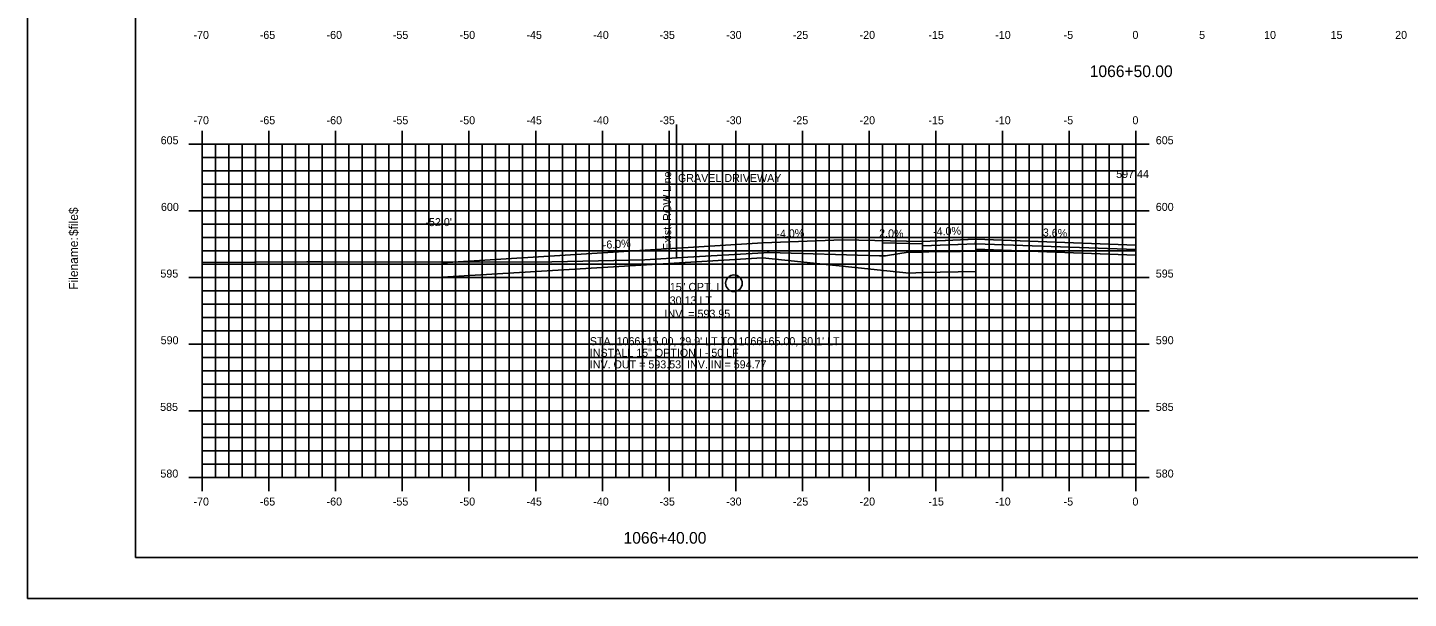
# Model space of a CAD drawing. Extents: x 1067877 to 1068047, y 779716 to 779826.
# Drawn here: x 1067877 to 1067980.5, y 779715.6 to 779758.5 of the extents above; entities that cross this region are included whole.
import ezdxf

# ---------------------------------------------------------------- set-up
doc = ezdxf.new("R2010")
doc.units = 0
for name, color, linetype in [('ANNOTATION', 7, 'Continuous'), ('BORDER', 7, 'Continuous'), ('D_Drainage_Culvert', 7, 'Continuous'), ('D_Roadway_Centerline', 7, 'Continuous'), ('D_Roadway_Centerline_Text', 7, 'Continuous'), ('D_Roadway_Drive_Gravel', 7, 'Continuous'), ('D_Roadway_Drive_SubGrade', 7, 'Continuous'), ('D_Roadway_Edge_Pavement', 7, 'Continuous'), ('D_Roadway_Edge_Shoulder', 7, 'Continuous'), ('D_Roadway_Pavement', 7, 'Continuous'), ('D_Roadway_SubGrade', 7, 'Continuous'), ('D_Text_Standard', 7, 'Continuous'), ('E_ROW_Line', 7, 'Continuous'), ('H_V ANNOTATION', 7, 'Continuous'), ('MAJOR', 7, 'Continuous'), ('MINOR', 7, 'Continuous'), ('PLOT BOUNDARY', 7, 'Continuous'), ('S_Roadway_Centerline', 7, 'Continuous')]:
    doc.layers.add(name, color=color, linetype=linetype)

msp = doc.modelspace()

# ---------------------------------------------------------------- linework, layer by layer
at = {"layer": 'BORDER'}
msp.add_lwpolyline([(1067885.05, 779718.71), (1068045.05, 779718.71), (1068045.05, 779823.71), (1067885.05, 779823.71)], close=True, dxfattribs=at)
at = {"layer": 'D_Drainage_Culvert'}
msp.add_circle((1067929.92, 779739.28), 0.625, dxfattribs=at)
at = {"layer": 'D_Roadway_Centerline'}
msp.add_lwpolyline([(1067944.05, 779742.42), (1067948.04, 779742.58), (1067948.05, 779742.58), (1067948.05, 779742.58), (1067960.05, 779742.15)], dxfattribs=at)
at = {"layer": 'D_Roadway_Drive_Gravel'}
for points in [[(1067944.05, 779742.42), (1067938.08, 779742.55), (1067932.08, 779742.31), (1067908.05, 779740.81)], [(1067944.05, 779742.25), (1067941.05, 779742.32), (1067941.05, 779742.48)]]:
    msp.add_lwpolyline(points, dxfattribs=at)
at = {"layer": 'D_Roadway_Drive_SubGrade'}
msp.add_lwpolyline([(1067944.05, 779740.08), (1067943.05, 779740.05), (1067932.05, 779741.2), (1067908.04, 779739.75), (1067908.04, 779740.87)], dxfattribs=at)
at = {"layer": 'D_Roadway_Edge_Pavement'}
for p, q in [((1067948.05, 779742.58), (1067960.05, 779742.15)), ((1067948.05, 779742.25), (1067960.05, 779741.81))]:
    msp.add_line(p, q, dxfattribs=at)
at = {"layer": 'D_Roadway_Edge_Shoulder'}
msp.add_lwpolyline([(1067948.05, 779742.58), (1067944.05, 779742.42), (1067944.05, 779742.09), (1067948.04, 779742.25)], close=True, dxfattribs=at)
at = {"layer": 'D_Roadway_Pavement'}
msp.add_line((1067948.05, 779741.83), (1067960.05, 779741.4), dxfattribs=at)
at = {"layer": 'D_Roadway_SubGrade'}
msp.add_lwpolyline([(1067948.05, 779740.16), (1067944.05, 779740.08), (1067944.05, 779742.09), (1067948.05, 779742.25), (1067948.05, 779742.09), (1067948.05, 779740.59)], close=True, dxfattribs=at)
at = {"layer": 'E_ROW_Line'}
msp.add_line((1067925.61, 779741.18), (1067925.61, 779751.18), dxfattribs=at)
msp.add_line((1067925.61, 779741.18), (1067925.61, 779751.18), dxfattribs=at)
at = {"layer": 'MAJOR'}
for p, q in [((1067890.05, 779750.71), (1067890.05, 779749.71)), ((1067895.05, 779750.71), (1067895.05, 779749.71)), ((1067900.05, 779750.71), (1067900.05, 779749.71)), ((1067905.05, 779750.71), (1067905.05, 779749.71)), ((1067910.05, 779750.71), (1067910.05, 779749.71)), ((1067915.05, 779750.71), (1067915.05, 779749.71)), ((1067920.05, 779750.71), (1067920.05, 779749.71)), ((1067925.05, 779750.71), (1067925.05, 779749.71)), ((1067930.05, 779750.71), (1067930.05, 779749.71)), ((1067935.05, 779750.71), (1067935.05, 779749.71)), ((1067940.05, 779750.71), (1067940.05, 779749.71)), ((1067945.05, 779750.71), (1067945.05, 779749.71)), ((1067950.05, 779750.71), (1067950.05, 779749.71)), ((1067955.05, 779750.71), (1067955.05, 779749.71)), ((1067960.05, 779750.71), (1067960.05, 779749.71)), ((1067889.04, 779749.71), (1067890.05, 779749.71)), ((1067890.05, 779749.71), (1067960.05, 779749.71)), ((1067890.05, 779724.71), (1067890.05, 779749.71)), ((1067890.05, 779724.71), (1067890.05, 779749.71)), ((1067890.05, 779749.71), (1067960.05, 779749.71)), ((1067895.05, 779724.71), (1067895.05, 779749.71)), ((1067900.05, 779724.71), (1067900.05, 779749.71)), ((1067905.05, 779724.71), (1067905.05, 779749.71)), ((1067910.05, 779724.71), (1067910.05, 779749.71)), ((1067915.05, 779724.71), (1067915.05, 779749.71)), ((1067920.05, 779724.71), (1067920.05, 779749.71)), ((1067925.05, 779724.71), (1067925.05, 779749.71)), ((1067930.05, 779724.71), (1067930.05, 779749.71)), ((1067935.05, 779724.71), (1067935.05, 779749.71)), ((1067940.05, 779724.71), (1067940.05, 779749.71)), ((1067945.05, 779724.71), (1067945.05, 779749.71)), ((1067950.05, 779724.71), (1067950.05, 779749.71)), ((1067955.05, 779724.71), (1067955.05, 779749.71)), ((1067961.05, 779749.71), (1067959.04, 779749.71)), ((1067960.05, 779724.71), (1067960.05, 779749.71)), ((1067960.05, 779724.71), (1067960.05, 779749.71)), ((1067889.04, 779744.71), (1067890.05, 779744.71)), ((1067890.05, 779744.71), (1067960.05, 779744.71)), ((1067961.05, 779744.71), (1067959.04, 779744.71)), ((1067889.04, 779739.71), (1067890.05, 779739.71)), ((1067890.05, 779739.71), (1067960.05, 779739.71)), ((1067961.05, 779739.71), (1067959.04, 779739.71)), ((1067889.04, 779734.71), (1067890.05, 779734.71)), ((1067890.05, 779734.71), (1067960.05, 779734.71)), ((1067961.05, 779734.71), (1067959.04, 779734.71)), ((1067889.04, 779729.71), (1067890.05, 779729.71)), ((1067890.05, 779729.71), (1067960.05, 779729.71)), ((1067961.05, 779729.71), (1067959.04, 779729.71)), ((1067889.04, 779724.71), (1067890.05, 779724.71)), ((1067890.05, 779724.71), (1067960.05, 779724.71)), ((1067890.05, 779724.71), (1067960.05, 779724.71)), ((1067890.05, 779723.7), (1067890.05, 779724.71)), ((1067895.05, 779723.7), (1067895.05, 779724.71)), ((1067900.05, 779723.7), (1067900.05, 779724.71)), ((1067905.05, 779723.7), (1067905.05, 779724.71)), ((1067910.05, 779723.7), (1067910.05, 779724.71)), ((1067915.05, 779723.7), (1067915.05, 779724.71)), ((1067920.05, 779723.7), (1067920.05, 779724.71)), ((1067925.05, 779723.7), (1067925.05, 779724.71)), ((1067930.05, 779723.7), (1067930.05, 779724.71)), ((1067935.05, 779723.7), (1067935.05, 779724.71)), ((1067940.05, 779723.7), (1067940.05, 779724.71)), ((1067945.05, 779723.7), (1067945.05, 779724.71)), ((1067950.05, 779723.7), (1067950.05, 779724.71)), ((1067955.05, 779723.7), (1067955.05, 779724.71)), ((1067961.05, 779724.71), (1067959.04, 779724.71)), ((1067960.05, 779723.7), (1067960.05, 779724.71))]:
    msp.add_line(p, q, dxfattribs=at)
at = {"layer": 'MINOR'}
for p, q in [((1067890.05, 779724.71), (1067890.05, 779749.71)), ((1067891.05, 779724.71), (1067891.05, 779749.71)), ((1067892.05, 779724.71), (1067892.05, 779749.71)), ((1067893.05, 779724.71), (1067893.05, 779749.71)), ((1067894.05, 779724.71), (1067894.05, 779749.71)), ((1067896.05, 779724.71), (1067896.05, 779749.71)), ((1067897.05, 779724.71), (1067897.05, 779749.71)), ((1067898.05, 779724.71), (1067898.05, 779749.71)), ((1067899.05, 779724.71), (1067899.05, 779749.71)), ((1067901.05, 779724.71), (1067901.05, 779749.71)), ((1067902.05, 779724.71), (1067902.05, 779749.71)), ((1067903.05, 779724.71), (1067903.05, 779749.71)), ((1067904.05, 779724.71), (1067904.05, 779749.71)), ((1067906.05, 779724.71), (1067906.05, 779749.71)), ((1067907.05, 779724.71), (1067907.05, 779749.71)), ((1067908.05, 779724.71), (1067908.05, 779749.71)), ((1067909.05, 779724.71), (1067909.05, 779749.71)), ((1067911.05, 779724.71), (1067911.05, 779749.71)), ((1067912.05, 779724.71), (1067912.05, 779749.71)), ((1067913.05, 779724.71), (1067913.05, 779749.71)), ((1067914.05, 779724.71), (1067914.05, 779749.71)), ((1067916.05, 779724.71), (1067916.05, 779749.71)), ((1067917.05, 779724.71), (1067917.05, 779749.71)), ((1067918.05, 779724.71), (1067918.05, 779749.71)), ((1067919.05, 779724.71), (1067919.05, 779749.71)), ((1067921.05, 779724.71), (1067921.05, 779749.71)), ((1067922.05, 779724.71), (1067922.05, 779749.71)), ((1067923.05, 779724.71), (1067923.05, 779749.71)), ((1067924.05, 779724.71), (1067924.05, 779749.71)), ((1067926.05, 779724.71), (1067926.05, 779749.71)), ((1067927.05, 779724.71), (1067927.05, 779749.71)), ((1067928.05, 779724.71), (1067928.05, 779749.71)), ((1067929.05, 779724.71), (1067929.05, 779749.71)), ((1067931.05, 779724.71), (1067931.05, 779749.71)), ((1067932.05, 779724.71), (1067932.05, 779749.71)), ((1067933.05, 779724.71), (1067933.05, 779749.71)), ((1067934.05, 779724.71), (1067934.05, 779749.71)), ((1067936.05, 779724.71), (1067936.05, 779749.71)), ((1067937.05, 779724.71), (1067937.05, 779749.71)), ((1067938.05, 779724.71), (1067938.05, 779749.71)), ((1067939.05, 779724.71), (1067939.05, 779749.71)), ((1067941.05, 779724.71), (1067941.05, 779749.71)), ((1067942.05, 779724.71), (1067942.05, 779749.71)), ((1067943.05, 779724.71), (1067943.05, 779749.71)), ((1067944.05, 779724.71), (1067944.05, 779749.71)), ((1067946.05, 779724.71), (1067946.05, 779749.71)), ((1067947.05, 779724.71), (1067947.05, 779749.71)), ((1067948.05, 779724.71), (1067948.05, 779749.71)), ((1067949.05, 779724.71), (1067949.05, 779749.71)), ((1067951.05, 779724.71), (1067951.05, 779749.71)), ((1067952.05, 779724.71), (1067952.05, 779749.71)), ((1067953.05, 779724.71), (1067953.05, 779749.71)), ((1067954.05, 779724.71), (1067954.05, 779749.71)), ((1067956.05, 779724.71), (1067956.05, 779749.71)), ((1067957.05, 779724.71), (1067957.05, 779749.71)), ((1067958.05, 779724.71), (1067958.05, 779749.71)), ((1067959.05, 779724.71), (1067959.05, 779749.71)), ((1067890.05, 779748.71), (1067960.05, 779748.71)), ((1067890.05, 779748.71), (1067891.05, 779748.71)), ((1067960.05, 779748.71), (1067959.04, 779748.71)), ((1067890.05, 779747.71), (1067960.05, 779747.71)), ((1067890.05, 779747.71), (1067891.05, 779747.71)), ((1067960.05, 779747.71), (1067959.04, 779747.71)), ((1067890.05, 779746.71), (1067960.05, 779746.71)), ((1067890.05, 779746.71), (1067891.05, 779746.71)), ((1067960.05, 779746.71), (1067959.04, 779746.71)), ((1067890.05, 779745.71), (1067960.05, 779745.71)), ((1067890.05, 779745.71), (1067891.05, 779745.71)), ((1067960.05, 779745.71), (1067959.04, 779745.71)), ((1067890.05, 779743.71), (1067960.05, 779743.71)), ((1067890.05, 779743.71), (1067891.05, 779743.71)), ((1067960.05, 779743.71), (1067959.04, 779743.71)), ((1067890.05, 779742.71), (1067960.05, 779742.71)), ((1067890.05, 779742.71), (1067891.05, 779742.71)), ((1067960.05, 779742.71), (1067959.04, 779742.71)), ((1067890.05, 779741.71), (1067960.05, 779741.71)), ((1067890.05, 779741.71), (1067891.05, 779741.71)), ((1067960.05, 779741.71), (1067959.04, 779741.71)), ((1067890.05, 779740.71), (1067960.05, 779740.71)), ((1067890.05, 779740.71), (1067891.05, 779740.71)), ((1067960.05, 779740.71), (1067959.04, 779740.71)), ((1067890.05, 779738.71), (1067960.05, 779738.71)), ((1067890.05, 779738.71), (1067891.05, 779738.71)), ((1067960.05, 779738.71), (1067959.04, 779738.71)), ((1067890.05, 779737.71), (1067960.05, 779737.71)), ((1067890.05, 779737.71), (1067891.05, 779737.71)), ((1067960.05, 779737.71), (1067959.04, 779737.71)), ((1067890.05, 779736.71), (1067960.05, 779736.71)), ((1067890.05, 779736.71), (1067891.05, 779736.71)), ((1067960.05, 779736.71), (1067959.04, 779736.71)), ((1067890.05, 779735.71), (1067960.05, 779735.71)), ((1067890.05, 779735.71), (1067891.05, 779735.71)), ((1067960.05, 779735.71), (1067959.04, 779735.71)), ((1067890.05, 779733.71), (1067960.05, 779733.71)), ((1067890.05, 779733.71), (1067891.05, 779733.71)), ((1067960.05, 779733.71), (1067959.04, 779733.71)), ((1067890.05, 779732.71), (1067960.05, 779732.71)), ((1067890.05, 779732.71), (1067891.05, 779732.71)), ((1067960.05, 779732.71), (1067959.04, 779732.71)), ((1067890.05, 779731.71), (1067960.05, 779731.71)), ((1067890.05, 779731.71), (1067891.05, 779731.71)), ((1067960.05, 779731.71), (1067959.04, 779731.71)), ((1067890.05, 779730.71), (1067960.05, 779730.71)), ((1067890.05, 779730.71), (1067891.05, 779730.71)), ((1067960.05, 779730.71), (1067959.04, 779730.71)), ((1067890.05, 779728.71), (1067960.05, 779728.71)), ((1067890.05, 779728.71), (1067891.05, 779728.71)), ((1067960.05, 779728.71), (1067959.04, 779728.71)), ((1067890.05, 779727.71), (1067960.05, 779727.71)), ((1067890.05, 779727.71), (1067891.05, 779727.71)), ((1067960.05, 779727.71), (1067959.04, 779727.71)), ((1067890.05, 779726.71), (1067960.05, 779726.71)), ((1067890.05, 779726.71), (1067891.05, 779726.71)), ((1067960.05, 779726.71), (1067959.04, 779726.71)), ((1067890.05, 779725.71), (1067960.05, 779725.71)), ((1067890.05, 779725.71), (1067891.05, 779725.71)), ((1067960.05, 779725.71), (1067959.04, 779725.71))]:
    msp.add_line(p, q, dxfattribs=at)
at = {"layer": 'PLOT BOUNDARY'}
msp.add_lwpolyline([(1067876.95, 779715.65), (1068046.95, 779715.65), (1068046.95, 779825.65), (1067876.95, 779825.65)], close=True, dxfattribs=at)
at = {"layer": 'S_Roadway_Centerline'}
msp.add_lwpolyline([(1067890.05, 779740.83), (1067897.89, 779740.88), (1067898.97, 779740.89), (1067915.12, 779740.86), (1067923.23, 779741.04), (1067926.45, 779741.23), (1067932.16, 779741.57), (1067932.4, 779741.58), (1067932.57, 779741.58), (1067940.83, 779741.33), (1067941.19, 779741.35), (1067941.28, 779741.35), (1067941.43, 779741.37), (1067942.97, 779741.62), (1067943.65, 779741.61), (1067943.72, 779741.61), (1067944.05, 779741.62), (1067944.54, 779741.64), (1067949.28, 779741.69), (1067953.28, 779741.68), (1067959.76, 779741.75), (1067960.05, 779741.73)], dxfattribs=at)

# ---------------------------------------------------------------- texts
at = {"layer": 'ANNOTATION'}
for s, rotation, p in [('-4.0%', 2.2903, (1067944.86, 779742.85)), ('-6.0%', 3.7807, (1067920.1, 779741.86)), ('-4.0%', 2.2903, (1067933.11, 779742.68)), ('2.0%', 358.8542, (1067940.8, 779742.74)), ('3.6%', 357.9379, (1067953.07, 779742.8))]:
    msp.add_text(s, height=0.6, rotation=rotation, dxfattribs=at).set_placement(p)
at = {"layer": 'BORDER'}
for s, p in [('$file$', (1067880.73, 779742.83)), ('Filename:', (1067880.73, 779738.8))]:
    msp.add_text(s, height=0.67, rotation=90, dxfattribs=at).set_placement(p)
at = {"layer": 'D_Roadway_Centerline_Text'}
for s, p in [('597.44', (1067958.58, 779747.18)), ('15" OPT. I', (1067925.11, 779738.71)), ('30.13 LT', (1067925.1, 779737.7)), ('INV. = 593.95', (1067924.71, 779736.7)), ("STA. 1066+15.00, 29.9' LT TO 1066+65.00, 30.1' LT", (1067919.11, 779734.64)), ('INSTALL 15" OPTION I - 50 LF', (1067919.11, 779733.77)), ('INV. OUT = 593.53, INV. IN = 594.77', (1067919.11, 779732.9))]:
    msp.add_text(s, height=0.6, dxfattribs=at).set_placement(p)
at = {"layer": 'D_Text_Standard'}
for s, p in [('GRAVEL DRIVEWAY', (1067925.72, 779746.88)), ("-52.0'", (1067906.78, 779743.57))]:
    msp.add_text(s, height=0.6, dxfattribs=at).set_placement(p)
at = {"layer": 'E_ROW_Line'}
msp.add_text('Exist. ROW Line', height=0.6, rotation=90, dxfattribs=at).set_placement((1067925.21, 779741.78))
at = {"layer": 'H_V ANNOTATION'}
for s, height, p in [('-70', 0.6, (1067889.39, 779757.61)), ('-65', 0.6, (1067894.36, 779757.61)), ('-60', 0.6, (1067899.37, 779757.61)), ('-55', 0.6, (1067904.34, 779757.61)), ('-50', 0.6, (1067909.35, 779757.61)), ('-45', 0.6, (1067914.36, 779757.61)), ('-40', 0.6, (1067919.37, 779757.61)), ('-35', 0.6, (1067924.33, 779757.61)), ('-30', 0.6, (1067929.33, 779757.61)), ('-25', 0.6, (1067934.33, 779757.61)), ('-20', 0.6, (1067939.34, 779757.61)), ('-15', 0.6, (1067944.5, 779757.61)), ('-10', 0.6, (1067949.51, 779757.61)), ('-5', 0.6, (1067954.64, 779757.61)), ('0', 0.6, (1067959.8, 779757.61)), ('5', 0.6, (1067964.8, 779757.61)), ('10', 0.6, (1067969.67, 779757.61)), ('15', 0.6, (1067974.66, 779757.61)), ('20', 0.6, (1067979.5, 779757.61)), ('1066+50.00', 0.875, (1067956.6, 779754.75)), ('-70', 0.6, (1067889.39, 779751.21)), ('-65', 0.6, (1067894.36, 779751.21)), ('-60', 0.6, (1067899.37, 779751.21)), ('-55', 0.6, (1067904.34, 779751.21)), ('-50', 0.6, (1067909.35, 779751.21)), ('-45', 0.6, (1067914.36, 779751.21)), ('-40', 0.6, (1067919.37, 779751.21)), ('-35', 0.6, (1067924.33, 779751.21)), ('-30', 0.6, (1067929.33, 779751.21)), ('-25', 0.6, (1067934.33, 779751.21)), ('-20', 0.6, (1067939.34, 779751.21)), ('-15', 0.6, (1067944.5, 779751.21)), ('-10', 0.6, (1067949.51, 779751.21)), ('-5', 0.6, (1067954.64, 779751.21)), ('0', 0.6, (1067959.8, 779751.21)), ('605', 0.6, (1067886.93, 779749.71)), ('605', 0.6, (1067961.55, 779749.71)), ('600', 0.6, (1067886.95, 779744.71)), ('600', 0.6, (1067961.55, 779744.71)), ('595', 0.6, (1067886.91, 779739.71)), ('595', 0.6, (1067961.55, 779739.71)), ('590', 0.6, (1067886.93, 779734.71)), ('590', 0.6, (1067961.55, 779734.71)), ('585', 0.6, (1067886.89, 779729.71)), ('585', 0.6, (1067961.55, 779729.71)), ('580', 0.6, (1067886.91, 779724.71)), ('580', 0.6, (1067961.55, 779724.71)), ('-70', 0.6, (1067889.39, 779722.61)), ('-65', 0.6, (1067894.36, 779722.61)), ('-60', 0.6, (1067899.37, 779722.61)), ('-55', 0.6, (1067904.34, 779722.61)), ('-50', 0.6, (1067909.35, 779722.61)), ('-45', 0.6, (1067914.36, 779722.61)), ('-40', 0.6, (1067919.37, 779722.61)), ('-35', 0.6, (1067924.33, 779722.61)), ('-30', 0.6, (1067929.33, 779722.61)), ('-25', 0.6, (1067934.33, 779722.61)), ('-20', 0.6, (1067939.34, 779722.61)), ('-15', 0.6, (1067944.5, 779722.61)), ('-10', 0.6, (1067949.51, 779722.61)), ('-5', 0.6, (1067954.64, 779722.61)), ('0', 0.6, (1067959.8, 779722.61)), ('1066+40.00', 0.875, (1067921.64, 779719.75))]:
    msp.add_text(s, height=height, dxfattribs=at).set_placement(p)
at = {"layer": 'MAJOR'}
msp.add_text('-', height=0.006, dxfattribs=at).set_placement((1067890.04, 779724.71))

doc.saveas('drawing.dxf')
